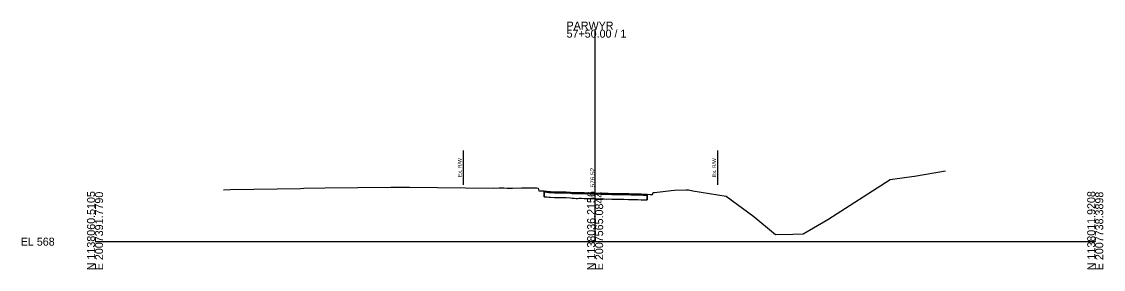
# Model space of a CAD drawing. Extents: x -2173 to 2007764, y -181 to 1138563.
# Drawn here: x 1017.4 to 1395.9, y 2990.3 to 3077 of the extents above; entities that cross this region are included whole.
import ezdxf

# ---------------------------------------------------------------- set-up
doc = ezdxf.new("R2010")
doc.units = 0
for name, color, linetype in [('Default', 7, 'Continuous'), ('RD_PD_Final_TrvlWay', 7, 'Continuous'), ('RD_PD_MedBWall', 7, 'Continuous'), ('RD_XS_ExPaveRet', 7, 'Continuous'), ('RD_XS_ExRW', 7, 'Continuous'), ('RD_XS_MedBWall', 7, 'Continuous'), ('RD_XS_TX_Elev_EX', 7, 'Continuous')]:
    doc.layers.add(name, color=color, linetype=linetype)

msp = doc.modelspace()

# ---------------------------------------------------------------- linework, layer by layer
at = {"layer": 'RD_PD_Final_TrvlWay'}
msp.add_lwpolyline([(1088.01, 3018.17), (1090.45, 3018.22), (1115.01, 3018.62), (1116.2, 3018.71), (1123.5, 3018.8), (1146.59, 3019.08), (1153.16, 3019.06), (1182.54, 3018.76), (1184.56, 3018.8), (1185.25, 3018.8), (1186.12, 3018.78), (1187.26, 3018.76), (1189.12, 3018.77), (1192.3, 3018.78), (1197.72, 3018.8), (1198.13, 3018.76), (1198.42, 3017.83), (1198.96, 3017.81), (1200.24, 3017.74), (1201.16, 3017.66), (1201.86, 3017.59), (1202.48, 3017.55), (1203.88, 3017.47), (1204.83, 3017.47), (1205.9, 3017.47), (1207.18, 3017.45), (1207.92, 3017.43), (1209.53, 3017.28), (1210.11, 3017.23), (1210.78, 3017.22), (1211.41, 3017.16), (1211.87, 3017.16), (1212.55, 3017.19), (1213.05, 3017.17), (1213.38, 3017.17), (1214.23, 3017.16), (1216, 3017.13), (1216.57, 3017.11), (1218.1, 3017.04), (1218.92, 3017.01), (1220.04, 3016.99), (1221.27, 3016.94), (1222.06, 3016.92), (1222.7, 3016.93), (1223.9, 3016.88), (1224.59, 3016.89), (1225.12, 3016.87), (1225.48, 3016.87), (1226.09, 3016.86), (1226.86, 3016.84), (1228.11, 3016.83), (1229.73, 3016.8), (1230.13, 3016.79), (1230.67, 3016.77), (1232.15, 3016.72), (1233.02, 3016.7), (1234.17, 3016.68), (1234.64, 3016.66), (1234.96, 3016.65), (1236.26, 3016.59), (1237.35, 3016.5), (1238.22, 3016.46), (1238.38, 3017.15), (1238.85, 3017.16), (1244.65, 3017.86), (1245.85, 3018.03), (1249.94, 3018.15), (1250.74, 3018.18), (1252.23, 3017.83), (1263.9, 3015.9), (1273.62, 3008.83), (1281.24, 3002.56), (1287.3, 3002.68), (1290.89, 3002.69), (1299.53, 3007.77), (1321.3, 3021.76), (1327.21, 3022.59), (1329.9, 3022.96), (1340.67, 3024.73)], dxfattribs=at)
at = {"layer": 'RD_PD_MedBWall'}
for p, q in [((1218.1, 3000), (1218.1, 3074.19)), ((1043.1, 3000), (1218.1, 3000)), ((1218.1, 3000), (1393.1, 3000))]:
    msp.add_line(p, q, dxfattribs=at)
at = {"layer": 'RD_XS_ExPaveRet'}
for p, q in [((1200.24, 3017.41), (1200.25, 3015.74)), ((1200.25, 3015.74), (1200.25, 3017.74)), ((1200.25, 3015.74), (1201.16, 3015.66)), ((1200.25, 3015.74), (1201.16, 3015.66)), ((1201.16, 3015.66), (1201.86, 3015.59)), ((1201.16, 3015.66), (1201.86, 3015.59)), ((1201.86, 3015.59), (1202.48, 3015.55)), ((1201.86, 3015.59), (1202.48, 3015.55)), ((1202.48, 3015.55), (1203.88, 3015.47)), ((1202.48, 3015.55), (1203.88, 3015.47)), ((1203.88, 3015.47), (1204.83, 3015.47)), ((1203.88, 3015.47), (1204.83, 3015.47)), ((1204.83, 3015.47), (1205.9, 3015.47)), ((1204.83, 3015.47), (1205.9, 3015.47)), ((1205.9, 3015.47), (1207.18, 3015.45)), ((1205.9, 3015.47), (1207.18, 3015.45)), ((1207.18, 3015.45), (1207.92, 3015.43)), ((1207.18, 3015.45), (1207.92, 3015.43)), ((1207.92, 3015.43), (1209.53, 3015.28)), ((1207.92, 3015.43), (1209.53, 3015.28)), ((1209.53, 3015.28), (1210.11, 3015.23)), ((1209.53, 3015.28), (1210.11, 3015.23)), ((1210.11, 3015.23), (1210.78, 3015.22)), ((1210.11, 3015.23), (1210.78, 3015.22)), ((1210.78, 3015.22), (1211.41, 3015.16)), ((1210.78, 3015.22), (1211.41, 3015.16)), ((1211.41, 3015.16), (1211.87, 3015.16)), ((1211.41, 3015.16), (1211.87, 3015.16)), ((1211.87, 3015.16), (1212.55, 3015.19)), ((1211.87, 3015.16), (1212.55, 3015.19)), ((1212.55, 3015.19), (1213.05, 3015.17)), ((1212.55, 3015.19), (1213.05, 3015.17)), ((1213.05, 3015.17), (1213.38, 3015.17)), ((1213.05, 3015.17), (1213.38, 3015.17)), ((1213.38, 3015.17), (1214.23, 3015.16)), ((1213.38, 3015.17), (1214.23, 3015.16)), ((1214.23, 3015.16), (1216, 3015.13)), ((1214.23, 3015.16), (1216, 3015.13)), ((1216, 3015.13), (1216.57, 3015.11)), ((1216, 3015.13), (1216.57, 3015.11)), ((1216.57, 3015.11), (1218.1, 3015.04)), ((1216.57, 3015.11), (1218.1, 3015.04)), ((1218.1, 3015.04), (1218.92, 3015.01)), ((1218.1, 3015.04), (1218.92, 3015.01)), ((1218.92, 3015.01), (1220.04, 3014.99)), ((1218.92, 3015.01), (1220.04, 3014.99)), ((1220.04, 3014.99), (1221.27, 3014.94)), ((1220.04, 3014.99), (1221.27, 3014.94)), ((1221.27, 3014.94), (1222.06, 3014.92)), ((1221.27, 3014.94), (1222.06, 3014.92)), ((1222.06, 3014.92), (1222.7, 3014.93)), ((1222.06, 3014.92), (1222.7, 3014.93)), ((1222.7, 3014.93), (1223.9, 3014.88)), ((1222.7, 3014.93), (1223.9, 3014.88)), ((1223.9, 3014.88), (1224.59, 3014.89)), ((1223.9, 3014.88), (1224.59, 3014.89)), ((1224.59, 3014.89), (1225.12, 3014.87)), ((1224.59, 3014.89), (1225.12, 3014.87)), ((1225.12, 3014.87), (1225.48, 3014.87)), ((1225.12, 3014.87), (1225.48, 3014.87)), ((1225.48, 3014.87), (1226.09, 3014.86)), ((1225.48, 3014.87), (1226.09, 3014.86)), ((1226.09, 3014.86), (1226.86, 3014.84)), ((1226.09, 3014.86), (1226.86, 3014.84)), ((1226.86, 3014.84), (1228.11, 3014.83)), ((1226.86, 3014.84), (1228.11, 3014.83)), ((1228.11, 3014.83), (1229.73, 3014.8)), ((1228.11, 3014.83), (1229.73, 3014.8)), ((1229.73, 3014.8), (1230.13, 3014.79)), ((1229.73, 3014.8), (1230.13, 3014.79)), ((1230.13, 3014.79), (1230.67, 3014.77)), ((1230.13, 3014.79), (1230.67, 3014.77)), ((1230.67, 3014.77), (1232.15, 3014.72)), ((1230.67, 3014.77), (1232.15, 3014.72)), ((1232.15, 3014.72), (1233.02, 3014.7)), ((1232.15, 3014.72), (1233.02, 3014.7)), ((1233.02, 3014.7), (1234.17, 3014.68)), ((1233.02, 3014.7), (1234.17, 3014.68)), ((1234.17, 3014.68), (1234.64, 3014.66)), ((1234.17, 3014.68), (1234.64, 3014.66)), ((1234.64, 3014.66), (1234.96, 3014.65)), ((1234.64, 3014.66), (1234.96, 3014.65)), ((1236.26, 3016.26), (1234.96, 3016.32)), ((1234.96, 3014.65), (1236.26, 3014.59)), ((1234.96, 3014.65), (1236.26, 3014.59)), ((1236.26, 3016.59), (1236.26, 3014.59)), ((1236.26, 3014.59), (1236.26, 3014.59))]:
    msp.add_line(p, q, dxfattribs=at)
for points in [[(1200.25, 3017.41), (1200.24, 3017.41)], [(1234.96, 3016.32), (1234.64, 3016.33), (1234.17, 3016.35), (1233.02, 3016.37), (1232.15, 3016.39), (1230.67, 3016.44), (1230.13, 3016.46), (1229.73, 3016.47), (1228.11, 3016.49), (1226.86, 3016.51), (1226.09, 3016.52), (1225.48, 3016.53), (1225.12, 3016.54), (1224.59, 3016.56), (1223.9, 3016.55), (1222.7, 3016.6), (1222.06, 3016.59), (1221.27, 3016.61), (1220.04, 3016.66), (1218.92, 3016.68), (1218.1, 3016.71), (1216.57, 3016.78), (1216, 3016.8), (1214.23, 3016.83), (1213.38, 3016.84), (1213.05, 3016.84), (1212.55, 3016.86), (1211.87, 3016.83), (1211.41, 3016.83), (1210.78, 3016.88), (1210.11, 3016.89), (1209.53, 3016.94), (1207.92, 3017.1), (1207.18, 3017.11), (1205.9, 3017.14), (1204.83, 3017.14), (1203.88, 3017.14), (1202.48, 3017.22), (1201.86, 3017.25), (1201.16, 3017.33), (1200.25, 3017.41)], [(1236.26, 3014.59), (1236.26, 3016.26), (1236.26, 3016.26)]]:
    msp.add_lwpolyline(points, dxfattribs=at)
at = {"layer": 'RD_XS_ExRW'}
for p, q in [((1171.88, 3031.87), (1171.88, 3019.87)), ((1260.87, 3031.87), (1260.87, 3019.87))]:
    msp.add_line(p, q, dxfattribs=at)
at = {"layer": 'RD_XS_MedBWall'}
for p, q in [((1200.25, 3017.74), (1200.25, 3017.41)), ((1236.26, 3016.59), (1236.26, 3016.26))]:
    msp.add_line(p, q, dxfattribs=at)
for points in [[(1200.25, 3017.74), (1201.16, 3017.66), (1201.86, 3017.59), (1202.48, 3017.55), (1203.88, 3017.47), (1204.83, 3017.47), (1205.9, 3017.47), (1207.18, 3017.45), (1207.92, 3017.43), (1209.53, 3017.28), (1210.11, 3017.23), (1210.78, 3017.22), (1211.41, 3017.16), (1211.87, 3017.16), (1212.55, 3017.19), (1213.05, 3017.17), (1213.38, 3017.17), (1214.23, 3017.16), (1216, 3017.13), (1216.57, 3017.11), (1218.1, 3017.04), (1218.92, 3017.01), (1220.04, 3016.99), (1221.27, 3016.94), (1222.06, 3016.92), (1222.7, 3016.93), (1223.9, 3016.88), (1224.59, 3016.89), (1225.12, 3016.87), (1225.48, 3016.87), (1226.09, 3016.86), (1226.86, 3016.84), (1228.11, 3016.83), (1229.73, 3016.8), (1230.13, 3016.79), (1230.67, 3016.77), (1232.15, 3016.72), (1233.02, 3016.7), (1234.17, 3016.68), (1234.64, 3016.66), (1234.96, 3016.65), (1236.26, 3016.59), (1236.26, 3016.59)], [(1200.25, 3017.41), (1201.16, 3017.33), (1201.86, 3017.25), (1202.48, 3017.22), (1203.88, 3017.14), (1204.83, 3017.14), (1205.9, 3017.14), (1207.18, 3017.11), (1207.92, 3017.1), (1209.53, 3016.94), (1210.11, 3016.89), (1210.78, 3016.88), (1211.41, 3016.83), (1211.87, 3016.83), (1212.55, 3016.86), (1213.05, 3016.84), (1213.38, 3016.84), (1214.23, 3016.83), (1216, 3016.8), (1216.57, 3016.78), (1218.1, 3016.71), (1218.92, 3016.68), (1220.04, 3016.66), (1221.27, 3016.61), (1222.06, 3016.59), (1222.7, 3016.6), (1223.9, 3016.55), (1224.59, 3016.56), (1225.12, 3016.54), (1225.48, 3016.53), (1226.09, 3016.52), (1226.86, 3016.51), (1228.11, 3016.49), (1229.73, 3016.47), (1230.13, 3016.46), (1230.67, 3016.44), (1232.15, 3016.39), (1233.02, 3016.37), (1234.17, 3016.35), (1234.64, 3016.33), (1234.96, 3016.32), (1236.26, 3016.26), (1236.26, 3016.26)]]:
    msp.add_lwpolyline(points, dxfattribs=at)

# ---------------------------------------------------------------- texts
at = {"layer": 'Default'}
msp.add_text('-', height=0.0001, dxfattribs=at).set_placement((1043.1, 3000))
at = {"layer": 'RD_PD_MedBWall'}
for s, p in [('57+50.00 / 1', (1208.1, 3071.39)), ('PARWYR', (1208.1, 3074.19)), ('EL 568', (1017.1, 2998.6))]:
    msp.add_text(s, height=2.8, dxfattribs=at).set_placement(p)
for s, p in [('N 1138060.5105', (1043.1, 2990)), ('E 2007391.7790', (1045.9, 2990)), ('N 1138036.2156', (1218.1, 2990)), ('E 2007565.0844', (1220.9, 2990)), ('N 1138011.9208', (1393.1, 2990)), ('E 2007738.3898', (1395.9, 2990))]:
    msp.add_text(s, height=2.8, rotation=90, dxfattribs=at).set_placement(p)
at = {"layer": 'RD_XS_ExRW'}
for p in [(1171.38, 3022.63), (1260.37, 3022.63)]:
    msp.add_text('Ex. R/W ', height=1.3, rotation=90, dxfattribs=at).set_placement(p)
at = {"layer": 'RD_XS_TX_Elev_EX'}
msp.add_text('576.52', height=1.6, rotation=90, dxfattribs=at).set_placement((1218, 3019.04))

doc.saveas('drawing.dxf')
